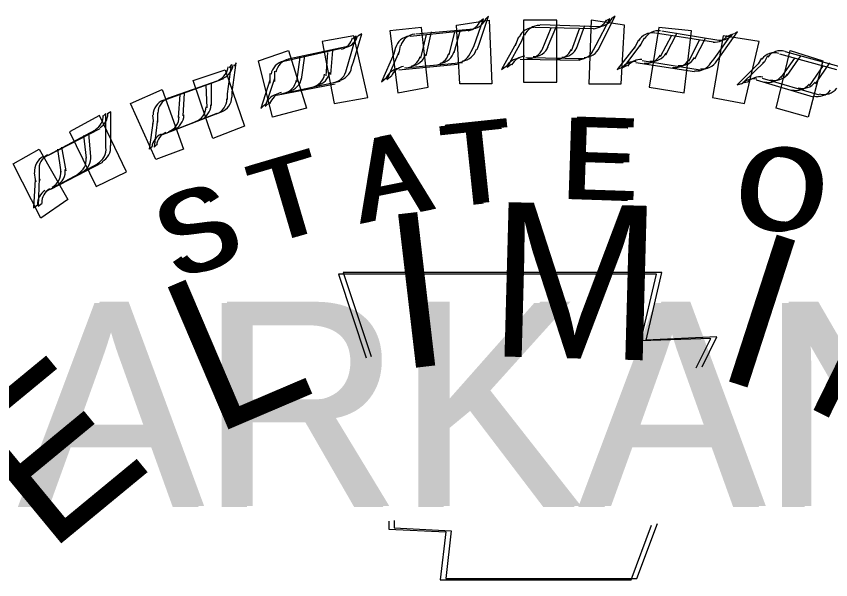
# Model space of a CAD drawing. Extents: x -194 to 226, y 505 to 725.
# Drawn here: x 58.75 to 66.24, y 535 to 540.18 of the extents above; entities that cross this region are included whole.
import ezdxf

# ---------------------------------------------------------------- set-up
doc = ezdxf.new("R2010")
doc.units = 0
for name, color, linetype in [('Border 2660-Hwy18 - STAMP PRELIM', 7, 'Continuous'), ('Border 2660-Hwy18 - Stamp-ChrisC', 7, 'Continuous'), ('Stamp Charles W', 7, 'Continuous')]:
    doc.layers.add(name, color=color, linetype=linetype)

msp = doc.modelspace()

# ---------------------------------------------------------------- linework, layer by layer
at = {"layer": 'Border 2660-Hwy18 - STAMP PRELIM'}
for p, q in [((62.4752, 540.0789), (62.1822, 540.0489)), ((62.5352, 539.5309), (62.4752, 540.0789)), ((62.7972, 540.1009), (63.0972, 540.1459)), ((62.8272, 539.5609), (62.7972, 540.1009)), ((63.0972, 540.1459), (63.1202, 539.5609)), ((63.7202, 540.1459), (63.4122, 540.1459)), ((63.4122, 540.1459), (63.4122, 539.5759)), ((63.7202, 539.5759), (63.7202, 540.1459)), ((64.0352, 540.1459), (64.0122, 539.5609)), ((64.3422, 540.1009), (64.0352, 540.1459)), ((64.3122, 539.5609), (64.3422, 540.1009)), ((64.6572, 540.0789), (64.5672, 539.5309)), ((64.9572, 540.0489), (64.6572, 540.0789)), ((61.8522, 540.0039), (61.5602, 539.9509)), ((61.9802, 539.4339), (61.8522, 540.0039)), ((62.1822, 540.0489), (62.2572, 539.4789)), ((64.8902, 539.4789), (64.9572, 540.0489)), ((65.2502, 540.0039), (65.1522, 539.4339)), ((65.5802, 539.9509), (65.2502, 540.0039)), ((61.5602, 539.9509), (61.6722, 539.3809)), ((65.4452, 539.3809), (65.5802, 539.9509)), ((60.9752, 539.7709), (61.2522, 539.8689)), ((61.2522, 539.8689), (61.4172, 539.3359)), ((65.7372, 539.3359), (65.8652, 539.8689)), ((65.8652, 539.8689), (66.1652, 539.7709)), ((61.1022, 539.2539), (60.9752, 539.7709)), ((66.1652, 539.7709), (66.0302, 539.2539)), ((60.3752, 539.5909), (60.6672, 539.6889)), ((60.6672, 539.6889), (60.8472, 539.1709)), ((60.5552, 539.0589), (60.3752, 539.5909)), ((63.1202, 539.5609), (62.8272, 539.5609)), ((63.4122, 539.5759), (63.7202, 539.5759)), ((64.0122, 539.5609), (64.3122, 539.5609)), ((59.7972, 539.3809), (60.0902, 539.5089)), ((60.0902, 539.5089), (60.2852, 538.9609)), ((62.2572, 539.4789), (62.5352, 539.5309)), ((64.5672, 539.5309), (64.8902, 539.4789)), ((61.6722, 539.3809), (61.9802, 539.4339)), ((65.1522, 539.4339), (65.4452, 539.3809)), ((60.0302, 538.8639), (59.7972, 539.3809)), ((61.4172, 539.3359), (61.1022, 539.2539)), ((66.0302, 539.2539), (65.7372, 539.3359)), ((59.5122, 539.2689), (59.2352, 539.1189)), ((59.7602, 538.7509), (59.5122, 539.2689)), ((59.2352, 539.1189), (59.4822, 538.6159)), ((60.8472, 539.1709), (60.5552, 539.0589)), ((58.7172, 538.8259), (58.9572, 538.9609)), ((58.9572, 538.9609), (59.2202, 538.4959)), ((60.2852, 538.9609), (60.0302, 538.8639)), ((58.9722, 538.3239), (58.7172, 538.8259)), ((59.4822, 538.6159), (59.7602, 538.7509)), ((59.2202, 538.4959), (58.9722, 538.3239))]:
    msp.add_line(p, q, dxfattribs=at)
at = {"layer": 'Border 2660-Hwy18 - Stamp-ChrisC'}
for p, q in [((62.9547, 539.9034), (63.0447, 540.1584)), ((63.0447, 540.1584), (63.0147, 540.1354)), ((64.0797, 539.9184), (64.2067, 540.1584)), ((64.2067, 540.1584), (64.1767, 540.1434)), ((63.5167, 540.0834), (64.0567, 540.0684)), ((63.5847, 539.8734), (63.6667, 540.0754)), ((63.8547, 539.8654), (63.9297, 540.0754)), ((61.7997, 539.7454), (61.8747, 540.0004)), ((61.8747, 540.0004), (61.8447, 539.9784)), ((62.3697, 540.0004), (62.9097, 540.0534)), ((62.4667, 539.7984), (62.5197, 540.0154)), ((62.7297, 539.8284), (62.7817, 540.0384)), ((64.6267, 540.0304), (65.1597, 539.9484)), ((64.6717, 539.8134), (64.7767, 540.0084)), ((65.1667, 539.7904), (65.3247, 540.0154)), ((65.3247, 540.0154), (65.2947, 540.0004)), ((63.3447, 539.9334), (63.2097, 539.6934)), ((63.3447, 539.9334), (63.3367, 539.9104)), ((63.3667, 539.9934), (63.3447, 539.9334)), ((64.4697, 539.9634), (64.4397, 539.9034)), ((64.9347, 539.7684), (65.0317, 539.9634)), ((61.2067, 539.7684), (61.7397, 539.8884)), ((61.5967, 539.6334), (61.6117, 539.8504)), ((62.2347, 539.8954), (62.2197, 539.8354)), ((62.9317, 539.8584), (62.9547, 539.9034)), ((64.0567, 539.8734), (64.0797, 539.9184)), ((64.4397, 539.9034), (64.2747, 539.6934)), ((64.4397, 539.9034), (64.4317, 539.8884)), ((61.3267, 539.5804), (61.3567, 539.8054)), ((62.2197, 539.8354), (62.1067, 539.5804)), ((62.2197, 539.8354), (62.2117, 539.8134)), ((63.9297, 539.7754), (63.3817, 539.7834)), ((65.1367, 539.7534), (65.1667, 539.7904)), ((65.6017, 539.7984), (65.5717, 539.7454)), ((65.7667, 539.8354), (66.2917, 539.6934)), ((65.7817, 539.6184), (65.9097, 539.7984)), ((60.6897, 539.4684), (60.7267, 539.7384)), ((60.7267, 539.7384), (60.7047, 539.7084)), ((61.7847, 539.6934), (61.7997, 539.7454)), ((62.8047, 539.7384), (62.2647, 539.6854)), ((63.2097, 539.6934), (63.2547, 539.7234)), ((64.2747, 539.6934), (64.3197, 539.7154)), ((64.9867, 539.6704), (64.4467, 539.7534)), ((65.5717, 539.7454), (65.3767, 539.5504)), ((65.5717, 539.7454), (65.5567, 539.7304)), ((66.0447, 539.5434), (66.1717, 539.7304)), ((61.0797, 539.6554), (61.0797, 539.5954)), ((60.0967, 539.4084), (60.6147, 539.5954)), ((60.5017, 539.3404), (60.4947, 539.5504)), ((61.0797, 539.5954), (60.9967, 539.3334)), ((61.0797, 539.5954), (61.0797, 539.5654)), ((61.6797, 539.5584), (61.1397, 539.4534)), ((62.1067, 539.5804), (62.1517, 539.6184)), ((65.3767, 539.5504), (65.4297, 539.5654)), ((66.0817, 539.4384), (65.5567, 539.5954)), ((60.2397, 539.2504), (60.2547, 539.4604)), ((60.6897, 539.4154), (60.6897, 539.4684)), ((60.9967, 539.3334), (61.0347, 539.3704)), ((59.5717, 539.2884), (59.5497, 539.2654)), ((59.5717, 539.0254), (59.5717, 539.2884)), ((59.9997, 539.2734), (60.0067, 539.2204)), ((60.5917, 539.2884), (60.0747, 539.0854)), ((60.0067, 539.2204), (59.9697, 538.9584)), ((60.0067, 539.2204), (59.9997, 539.1904)), ((59.0017, 538.8834), (59.4747, 539.1384)), ((59.3917, 538.8754), (59.3697, 539.0854)), ((59.5717, 538.9734), (59.5717, 539.0254)), ((59.1597, 538.7484), (59.1297, 538.9584)), ((59.9697, 538.9584), (59.9997, 538.9884)), ((59.4967, 538.8234), (59.0167, 538.5684)), ((58.9117, 538.7404), (58.9197, 538.6804)), ((58.9197, 538.6804), (58.9047, 538.4184)), ((58.9197, 538.6804), (58.9267, 538.6584)), ((58.9047, 538.4184), (58.9417, 538.4484))]:
    msp.add_line(p, q, dxfattribs=at)
for points in [[(61.7097, 537.8104), (61.9647, 537.0384)], [(65.0017, 536.9484), (65.1367, 537.2184), (64.4917, 537.1954), (64.6347, 537.8104), (61.7097, 537.8104)], [(62.1747, 535.5384), (62.1747, 535.4634), (62.6997, 535.4404), (62.6467, 534.9984), (64.4017, 534.9984), (64.5897, 535.5004)]]:
    msp.add_lwpolyline(points, dxfattribs=at)
for centre, start, end in [((62.8787, 540.1955), 279.92492, 338.71276), ((63.5082, 539.9307), 89.16284, 157.53681), ((64.045, 540.2159), 273.42361, 332.21146), ((64.5985, 539.8816), 81.42307, 149.79704), ((65.1689, 540.0919), 265.68385, 324.47169), ((61.696, 540.021), 286.27006, 345.0579), ((62.3776, 539.8514), 95.66414, 164.03812), ((62.7874, 539.9002), 275.66414, 344.03812), ((63.4513, 539.9401), 269.16284, 337.53681), ((63.7156, 539.9352), 269.16284, 337.53681), ((63.9209, 539.9328), 269.16284, 337.53681), ((62.32, 539.8543), 275.66414, 344.03812), ((62.5831, 539.8793), 275.66414, 344.03812), ((63.3841, 539.6477), 93.42361, 152.21146), ((64.5434, 539.8986), 261.42307, 329.79704), ((64.8046, 539.8582), 261.42307, 329.79704), ((65.7213, 539.6985), 73.99093, 142.3649), ((60.5491, 539.7333), 294.83706, 353.62491), ((61.2361, 539.6236), 102.00928, 170.38325), ((62.2863, 539.5561), 99.92492, 158.71276), ((64.4374, 539.6179), 85.68385, 144.47169), ((65.0077, 539.8282), 261.42307, 329.79704), ((61.4373, 539.6742), 282.00928, 350.38325), ((61.638, 539.7175), 282.00928, 350.38325), ((65.6688, 539.7225), 253.99093, 322.3649), ((61.1785, 539.6201), 282.00928, 350.38325), ((65.5275, 539.4578), 78.25171, 137.03955), ((65.9227, 539.6486), 253.99093, 322.3649), ((66.1202, 539.5926), 253.99093, 322.3649), ((60.1535, 539.2718), 110.57629, 178.95026), ((60.5369, 539.4244), 290.57629, 358.95026), ((61.178, 539.3201), 106.27006, 165.0579), ((60.3449, 539.3517), 290.57629, 358.95026), ((59.3982, 539.2675), 301.95449, 0.74233), ((60.097, 539.2597), 290.57629, 358.95026), ((60.1413, 538.9629), 114.83706, 173.62491), ((59.4244, 538.9596), 297.69371, 6.06769), ((59.0628, 538.7606), 117.69371, 186.06769), ((59.2428, 538.8636), 297.69371, 6.06769), ((59.0083, 538.7417), 297.69371, 6.06769), ((59.0889, 538.4526), 121.95449, 180.74233)]:
    msp.add_arc(centre, 0.1481, start, end, dxfattribs=at)
at = {"layer": 'Stamp Charles W'}
for p, q in [((63.0042, 539.9245), (63.0901, 540.1822)), ((63.0901, 540.1822), (63.0615, 540.1536)), ((64.1306, 539.934), (64.2547, 540.1822)), ((64.2547, 540.1822), (64.2261, 540.1631)), ((63.5674, 540.1059), (64.1115, 540.0868)), ((63.6342, 539.8958), (63.7201, 540.0963)), ((63.9015, 539.8863), (63.9779, 540.0963)), ((61.8491, 539.7622), (61.9254, 540.0199)), ((61.9254, 540.0199), (61.8873, 540.0008)), ((62.4219, 540.0199), (62.9564, 540.0677)), ((62.5173, 539.8195), (62.565, 540.039)), ((62.7751, 539.8481), (62.8323, 540.0581)), ((63.4147, 540.0104), (63.3956, 539.9531)), ((64.6843, 540.0486), (65.2094, 539.9627)), ((64.7225, 539.829), (64.8275, 540.0295)), ((65.2189, 539.8099), (65.3812, 540.039)), ((65.3812, 540.039), (65.3526, 540.0199)), ((62.9851, 539.8767), (63.0042, 539.9245)), ((63.3956, 539.9531), (63.2619, 539.7145)), ((63.3956, 539.9531), (63.386, 539.934)), ((64.1115, 539.8958), (64.1306, 539.934)), ((64.4934, 539.9245), (64.3311, 539.7145)), ((64.4934, 539.9245), (64.4838, 539.9054)), ((64.522, 539.9818), (64.4934, 539.9245)), ((64.9898, 539.7908), (65.0853, 539.9818)), ((61.2477, 539.7908), (61.7823, 539.9054)), ((61.6391, 539.6476), (61.6582, 539.8672)), ((62.2691, 539.8576), (62.1546, 539.5999)), ((62.2691, 539.8576), (62.2596, 539.829)), ((62.2787, 539.9149), (62.2691, 539.8576)), ((65.8203, 539.8576), (66.3454, 539.7145)), ((61.3718, 539.5999), (61.4004, 539.8195)), ((63.9779, 539.7908), (63.4338, 539.8004)), ((65.1903, 539.7717), (65.2189, 539.8099)), ((65.658, 539.8195), (65.6294, 539.7622)), ((65.8394, 539.6381), (65.9635, 539.8195)), ((60.7322, 539.4853), (60.7704, 539.7526)), ((60.7704, 539.7526), (60.7513, 539.724)), ((61.83, 539.7145), (61.8491, 539.7622)), ((62.8514, 539.7526), (62.3168, 539.7049)), ((63.2619, 539.7145), (63.3001, 539.7431)), ((64.3311, 539.7145), (64.3693, 539.7335)), ((65.0375, 539.6858), (64.5029, 539.7717)), ((65.6294, 539.7622), (65.4289, 539.5713)), ((65.6294, 539.7622), (65.6103, 539.7526)), ((66.0972, 539.5617), (66.2308, 539.7526)), ((61.1236, 539.6763), (61.1236, 539.6094)), ((62.1546, 539.5999), (62.2023, 539.6381)), ((60.1403, 539.4281), (60.6558, 539.6094)), ((60.5412, 539.3612), (60.5412, 539.5713)), ((61.1236, 539.6094), (61.0376, 539.3517)), ((61.1236, 539.6094), (61.1236, 539.5808)), ((61.725, 539.5808), (61.1808, 539.4663)), ((65.4289, 539.5713), (65.4862, 539.5808)), ((66.1354, 539.4567), (65.6103, 539.6094)), ((60.2835, 539.2658), (60.293, 539.4758)), ((60.7322, 539.4376), (60.7322, 539.4853)), ((61.0376, 539.3517), (61.0758, 539.3899)), ((59.6153, 539.304), (59.5866, 539.2849)), ((59.6153, 539.0462), (59.6153, 539.304)), ((60.0448, 539.2944), (60.0448, 539.2371)), ((60.6367, 539.304), (60.1212, 539.1035)), ((60.0448, 539.2371), (60.0162, 538.9794)), ((60.0448, 539.2371), (60.0448, 539.2085)), ((59.0425, 538.903), (59.5198, 539.1512)), ((59.4339, 538.8935), (59.4148, 539.1035)), ((59.6153, 538.9889), (59.6153, 539.0462)), ((59.2048, 538.7598), (59.1666, 538.9794)), ((60.0162, 538.9794), (60.0448, 539.008)), ((59.5389, 538.8362), (59.0616, 538.588)), ((58.9566, 538.7598), (58.9566, 538.693)), ((58.9566, 538.693), (58.947, 538.4353)), ((58.9566, 538.693), (58.9661, 538.6739)), ((58.947, 538.4353), (58.9852, 538.4639))]:
    msp.add_line(p, q, dxfattribs=at)
for points in [[(61.7536, 537.8243), (62.0114, 537.051)], [(65.0566, 536.9556), (65.1903, 537.2324), (64.5411, 537.2038), (64.6843, 537.8243), (61.7536, 537.8243)], [(62.2214, 535.5427), (62.2214, 535.4759), (62.7464, 535.4473), (62.6987, 535.0081), (64.4552, 535.0081), (64.6461, 535.5141)]]:
    msp.add_lwpolyline(points, dxfattribs=at)
for centre, start, end in [((62.9285, 540.2151), 279.92492, 338.71276), ((64.0975, 540.2355), 273.42361, 332.21146), ((63.5594, 539.9497), 89.16284, 157.53681), ((61.7432, 540.0402), 286.27006, 345.0579), ((62.4263, 539.8702), 95.66414, 164.03812), ((64.6522, 539.9005), 81.42307, 149.79704), ((65.2238, 540.1113), 265.68385, 324.47169), ((62.6323, 539.8982), 275.66414, 344.03812), ((62.837, 539.9191), 275.66414, 344.03812), ((63.5024, 539.9591), 269.16284, 337.53681), ((63.7673, 539.9542), 269.16284, 337.53681), ((63.9731, 539.9518), 269.16284, 337.53681), ((65.7775, 539.717), 73.99093, 142.3649), ((61.2822, 539.642), 102.00928, 170.38325), ((62.3685, 539.8731), 275.66414, 344.03812), ((63.435, 539.666), 93.42361, 152.21146), ((64.4907, 539.6362), 85.68385, 144.47169), ((64.5969, 539.9175), 261.42307, 329.79704), ((64.8588, 539.877), 261.42307, 329.79704), ((60.5938, 539.7518), 294.83706, 353.62491), ((61.685, 539.736), 282.00928, 350.38325), ((62.3348, 539.5742), 99.92492, 158.71276), ((65.0623, 539.8469), 261.42307, 329.79704), ((61.4839, 539.6926), 282.00928, 350.38325), ((65.7249, 539.741), 253.99093, 322.3649), ((61.2245, 539.6384), 282.00928, 350.38325), ((65.5832, 539.4758), 78.25171, 137.03955), ((65.9793, 539.667), 253.99093, 322.3649), ((61.224, 539.3377), 106.27006, 165.0579), ((66.1773, 539.6108), 253.99093, 322.3649), ((60.1972, 539.2893), 110.57629, 178.95026), ((60.5815, 539.4423), 290.57629, 358.95026), ((60.3891, 539.3694), 290.57629, 358.95026), ((59.4403, 539.2851), 301.95449, 0.74233), ((60.1407, 539.2772), 290.57629, 358.95026), ((60.185, 538.9798), 114.83706, 173.62491), ((59.4665, 538.9764), 297.69371, 6.06769), ((59.1041, 538.777), 117.69371, 186.06769), ((59.2846, 538.8802), 297.69371, 6.06769), ((59.0495, 538.758), 297.69371, 6.06769), ((59.1303, 538.4683), 121.95449, 180.74233)]:
    msp.add_arc(centre, 0.1484, start, end, dxfattribs=at)

# ---------------------------------------------------------------- texts
at = {"layer": 'Border 2660-Hwy18 - STAMP PRELIM'}
for s, rotation, p in [('M', 358.46666, (63.0822, 537.0559)), ('I', 6.67523, (62.2502, 536.9289)), ('I', 342.04953, (65.1372, 536.8759)), ('N', 333.84096, (65.9402, 536.6289)), ('L', 23.09236, (60.5552, 536.3209)), ('E', 39.5095, (59.0402, 535.2339))]:
    msp.add_text(s, height=1.4209, rotation=rotation, dxfattribs=at).set_placement(p)
at = {"layer": 'Border 2660-Hwy18 - Stamp-ChrisC'}
for s, height, rotation, p in [('E', 0.7499, 358.07323, (63.7447, 538.5034)), ('T', 0.75, 6.02276, (62.6947, 538.4214)), ('A', 0.75, 11.21318, (61.9067, 538.2714)), ('T', 0.7499, 16.4036, (61.0367, 538.0684)), ('O', 0.7498, 350.4515, (65.3117, 538.2784)), ('S', 0.7499, 21.59401, (60.2117, 537.7384))]:
    msp.add_text(s, height=height, rotation=rotation, dxfattribs=at).set_placement(p)
msp.add_text('ARKANSAS', height=1.87497, dxfattribs=at).set_placement((58.7567, 535.6684))
at = {"layer": 'Stamp Charles W'}
for s, height, rotation, p in [('E', 0.7515, 358.07323, (63.7965, 538.5116)), ('T', 0.7517, 6.02276, (62.7464, 538.4353)), ('A', 0.7517, 11.21318, (61.9541, 538.2825)), ('T', 0.7515, 16.4036, (61.0854, 538.082)), ('O', 0.7514, 350.4515, (65.3717, 538.2921)), ('S', 0.7515, 21.59401, (60.2644, 537.7479))]:
    msp.add_text(s, height=height, rotation=rotation, dxfattribs=at).set_placement(p)
msp.add_text('ARKANSAS', height=1.87911, dxfattribs=at).set_placement((58.8038, 535.6764))

doc.saveas('drawing.dxf')
